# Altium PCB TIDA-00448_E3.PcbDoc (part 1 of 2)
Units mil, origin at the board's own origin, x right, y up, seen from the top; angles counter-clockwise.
Board outline 2125 x 2550 mil, 4 copper layers (Top Layer, MidLayer1, MidLayer2, Bottom Layer), stack 90 mil thick; 140 components, 62 nets, 330 pads, 116 vias.
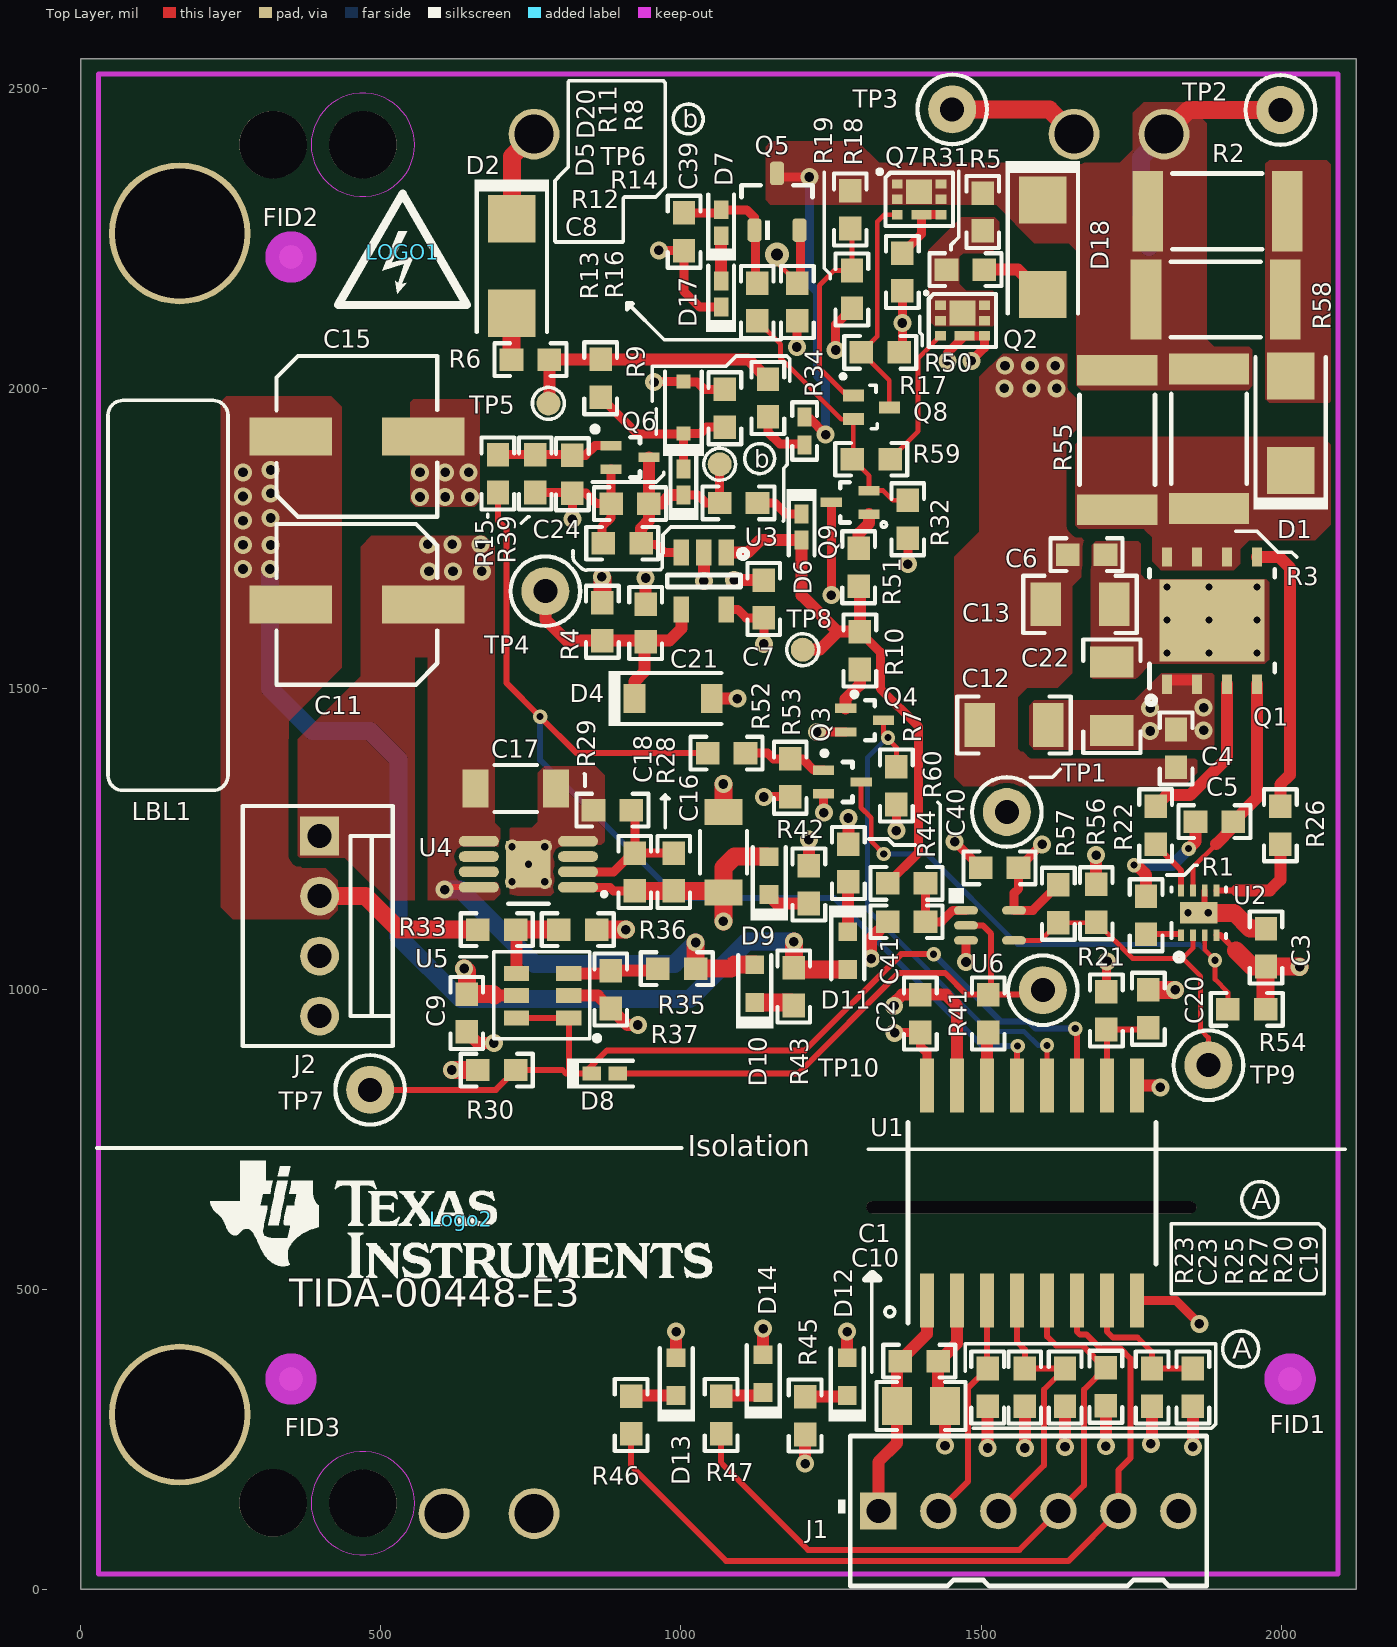
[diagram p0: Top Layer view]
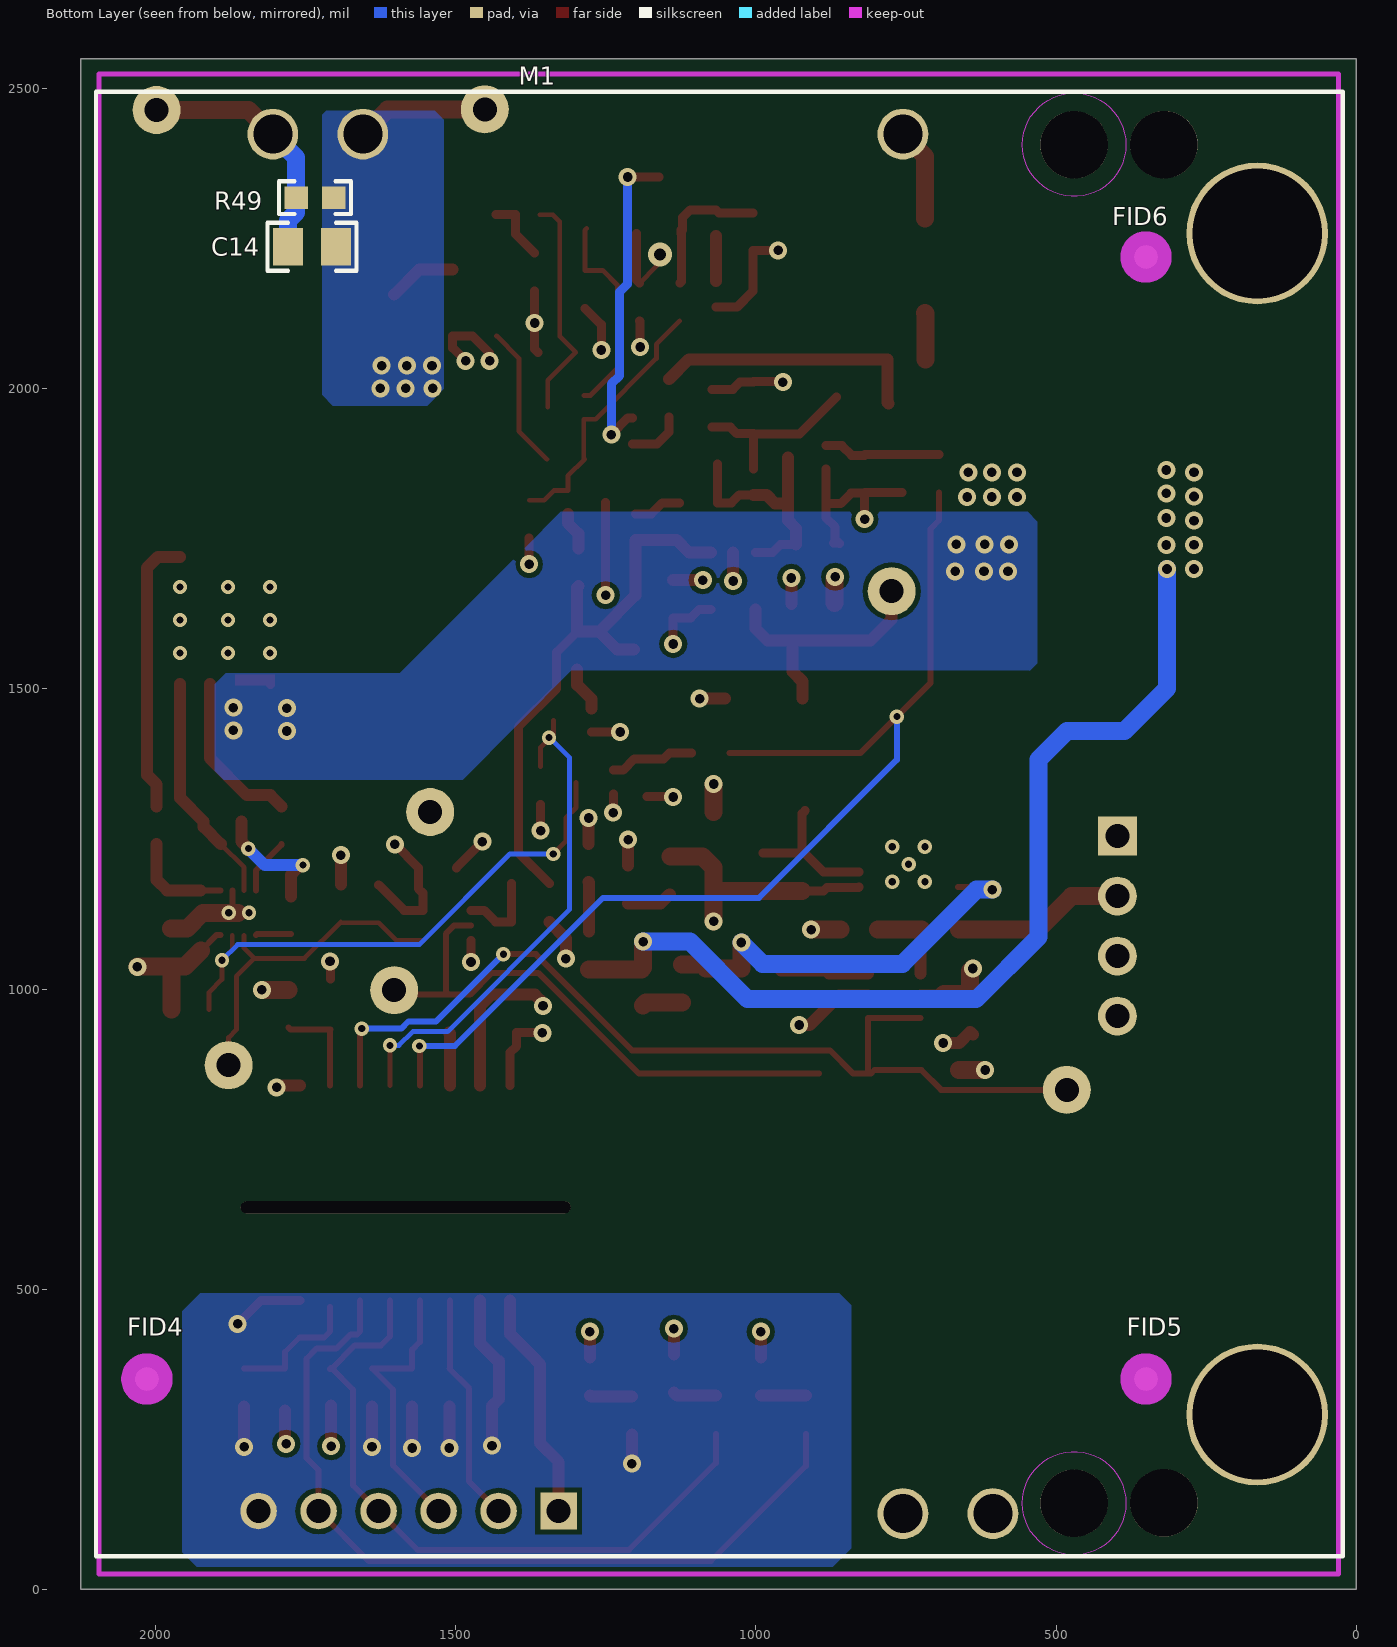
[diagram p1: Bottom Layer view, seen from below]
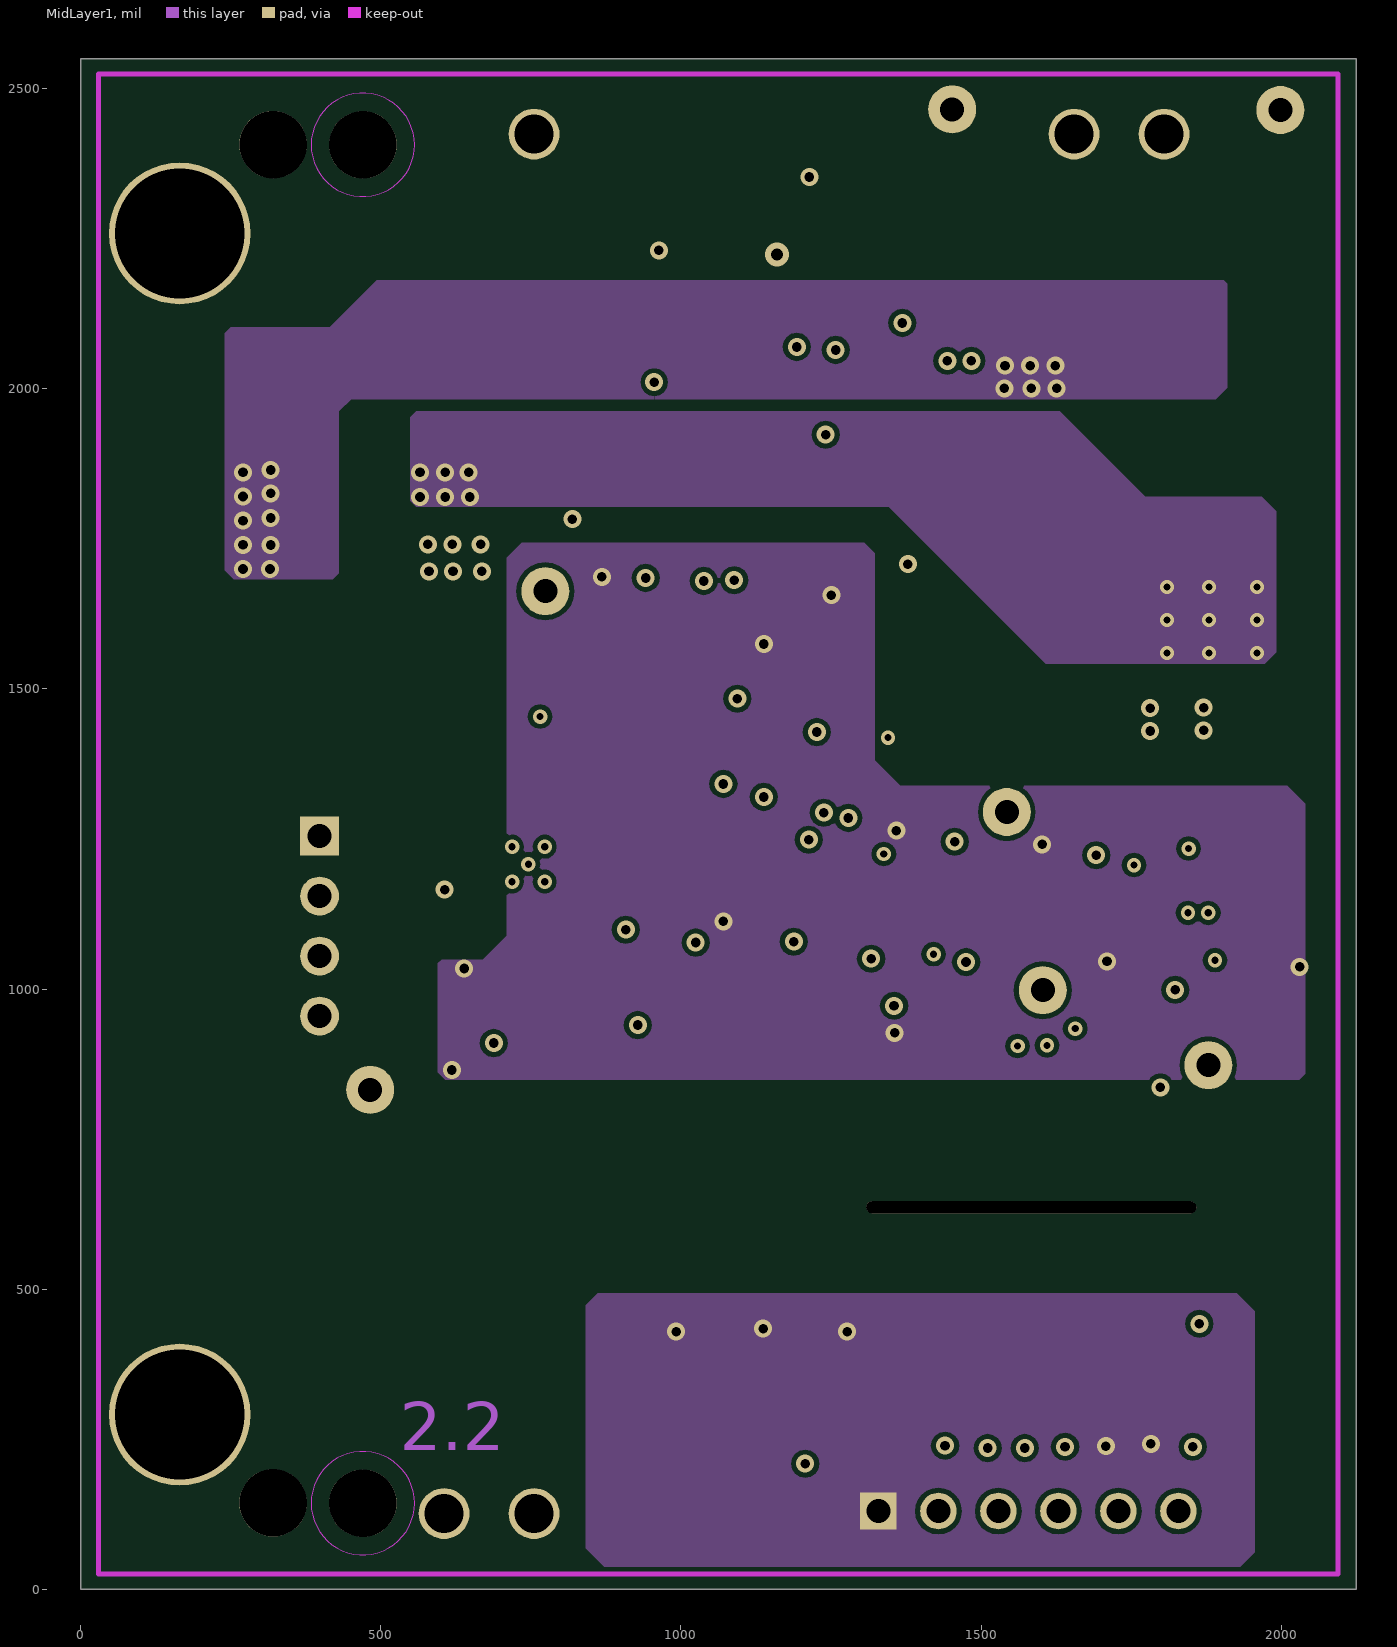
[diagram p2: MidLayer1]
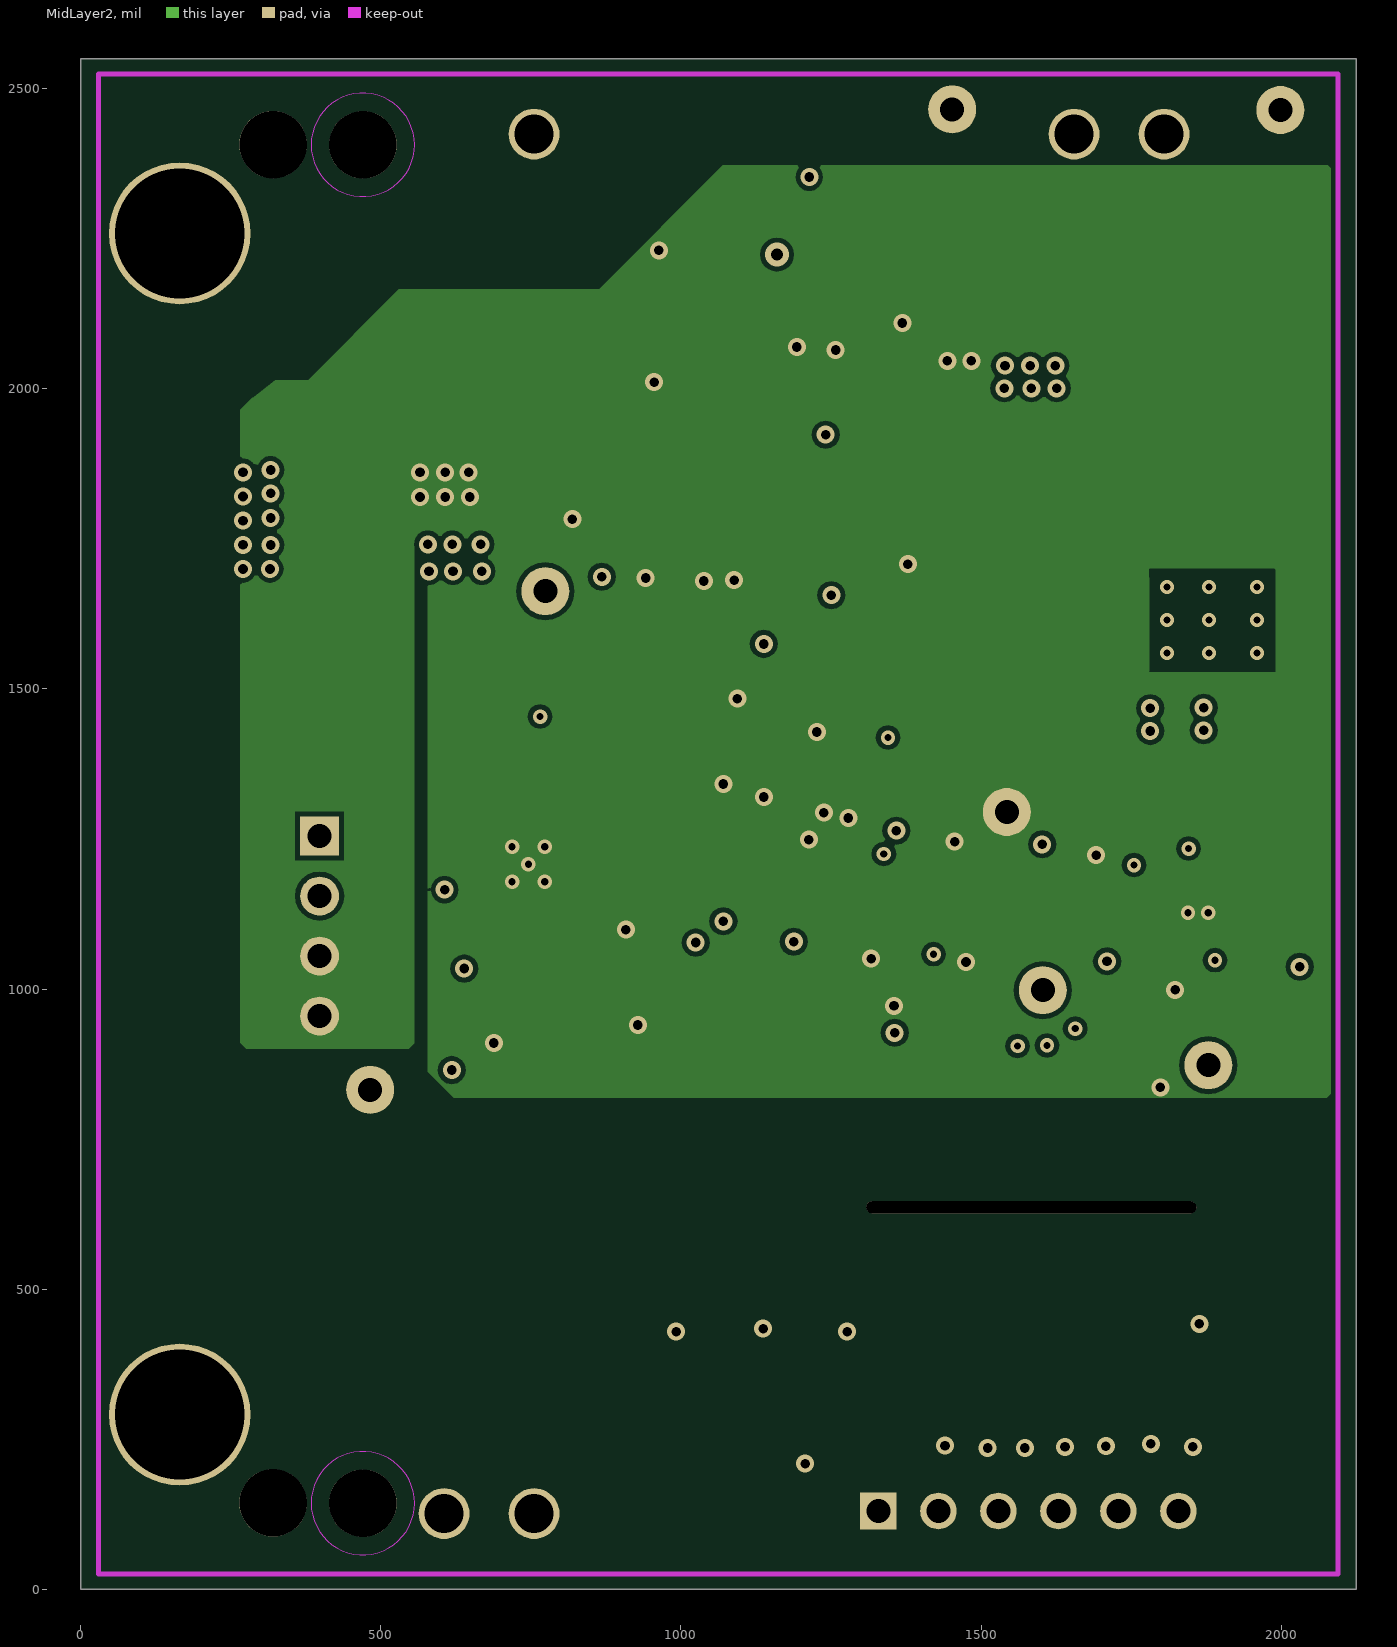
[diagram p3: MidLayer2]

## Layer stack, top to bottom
Top Layer: signal copper 1.4
Dielectric: core 59.2, FR-4, Dk 4.8
MidLayer1: signal copper 1.4
Dielectric: prepreg 12.6, FR-4, Dk 4.8
MidLayer2: signal copper 1.4
Dielectric: core 12.6, FR-4, Dk 4.8
Bottom Layer: signal copper 1.4

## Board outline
0,0 0,2550 2125,2550 2125,0

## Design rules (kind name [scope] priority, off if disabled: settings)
AcuteAngle [All] p1: minimum=4.50000000000000E+0001 checktracksonly=FALSE
AssemblyTestPointUsage [All] p1: valid=2
Clearance Poly_Poly [InPolygon vs InPolygon] p1: gap=15
Clearance "Poly_ All" [InPolygon] p2: gap=8
Clearance "Less Than 9 mils from PAD to PAD" [(InPadClass('Less than 9 Mil Clearance')) vs (InPadClass('Less than 9 Mil Clearance'))] p3: gap=7.8
Clearance "SMT Pin Via" [IsVia vs IsSMTPin] p4: gap=8
Clearance "Via to Via" [IsVia vs IsVia] p5: gap=8
Clearance [All] p6: gap=8
ComponentClearance ComponentClearance_Shunt [InComponentClass('Header') vs InComponentClass('Shunt')] p1: gap=0 collisioncheckmode=3 verticalgap=0 showdistances=FALSE
ComponentClearance ComponentClearance_Logo [InComponentClass('Logo')] p2: gap=50 collisioncheckmode=3 verticalgap=10 showdistances=FALSE
ComponentClearance ComponentClearance_ScrewToNut [(HasFootprint('NY PMS 440 0025 PH')) vs (HasFootprint('Keystone_1902C'))] p3: gap=5 collisioncheckmode=3 verticalgap=10 showdistances=FALSE
ComponentClearance ComponentClearance_MountingHoles [InComponentClass('Mounting Holes')] p4: gap=250 collisioncheckmode=3 verticalgap=100000 showdistances=FALSE
ComponentClearance ComponentClearance_SmallPassives [HasFootprint('0201*') or HasFootprint('0402*') or HasFootprint('0508') or HasFootprint('0603*') or HasFootprint('0612') or HasFootprint('0805*') or HasFootprint('0815*') or HasFootprint('0830*') or HasFootprint('1206*') or HasFootprint('1210*') or HasFootprint('1808*') or HasFootprint('1812*') or HasFootprint('1825*') or HasFootprint('2010*') or HasFootprint('2220*') or HasFootprint('2225*') or HasFootprint('2512*') or HasFootprint('2728*') or HasFootprint('3518*') vs HasFootprint('0201*') or HasFootprint('0402*') or HasFootprint('0508') or HasFootprint('0603*') or HasFootprint('0612') or HasFootprint('0805*') or HasFootprint('0815*') or HasFootprint('0830*') or HasFootprint('1206*') or HasFootprint('1210*') or HasFootprint('1808*') or HasFootprint('1812*') or HasFootprint('1825*') or HasFootprint('2010*') or HasFootprint('2220*') or HasFootprint('2225*') or HasFootprint('2512*') or HasFootprint('2728*') or HasFootprint('3518*')] p5: gap=20 collisioncheckmode=3 verticalgap=10 showdistances=FALSE
ComponentClearance ComponentClearance_THtoSMT [IsThruComponent vs IsSMTComponent] p6: gap=100 collisioncheckmode=3 verticalgap=30 showdistances=FALSE
ComponentClearance ComponentClearance_THtoTH [IsThruComponent vs IsThruComponent] p7: gap=118.11 collisioncheckmode=3 verticalgap=30 showdistances=FALSE
ComponentClearance [All] p8: gap=40 collisioncheckmode=3 verticalgap=10 showdistances=FALSE
DiffPairsRouting [All] p1: maxlimit=100 minlimit=10 mostfreqgap=10 maxuncoupledlength=1000
FabricationTestPointUsage TestPointUsage [All] p1: valid=2 allowmultiple=FALSE
FabricationTestpoint Testpoint [All] p1: side=3 testpointundercomponent=TRUE minsize=40 maxsize=100 preferedsize=60 minholesize=0 maxholesize=40 preferedholesize=32 testpointgrid=1 allowsidetop=TRUE allowsidebottom=TRUE usegrid=TRUE gridtolerance=0.01
FanoutControl Fanout_LCC [IsLCC] p1: bgadir=Out bgaviamode=Centered fanoutstyle=Auto fanoutdirection=Alternating viagrid=1 // Fanout_LCC (Default Rule)
FanoutControl Fanout_BGA [IsBGA] p2: bgadir=Out bgaviamode=Centered fanoutstyle=Auto fanoutdirection=Alternating viagrid=1 // Fanout_BGA (Default Rule)
FanoutControl Fanout_Default [All] p4: bgadir=Out bgaviamode=Centered fanoutstyle=Auto fanoutdirection=Alternating viagrid=1 // Fanout_Default (Default Rule)
FanoutControl Fanout_Small [(CompPinCount < 5)] p5: bgadir=Out bgaviamode=Centered fanoutstyle=Auto fanoutdirection=OutThenIn viagrid=1 // Fanout_Small (Default Rule)
HoleSize [All] p1: absolutevalues=TRUE maxlimit=251 minlimit=7.87 maxpercent=80.000 minpercent=20.000
MinimumAnnularRing MinimumAnnularRing_ThermalPadVias [IsVia and InAnyComponent] p1: minimumring=5.91
MinimumAnnularRing [All] p2: minimumring=5.91
MinimumSolderMaskSliver MinimumSolderMaskSliver_Logo [InComponentClass('Logo') vs InComponentClass('Logo')] p1: minsoldermaskwidth=0.7
MinimumSolderMaskSliver [All] p2: minsoldermaskwidth=3.94
PlaneConnect [All] p1: planeconnectstyle=Relief reliefexpansion=10 reliefentries=4 reliefconductorwidth=10 reliefairgap=10
PolygonConnect [All] p1: connectstyle=Direct reliefconductorwidth=10 reliefentries=4 polygonreliefangle="90 Angle" airgapwidth=10
RoutingVias [All] p1: holewidth=16 width=30 viastyle="Through Hole" minholewidth=12 minwidth=24 maxholewidth=20 maxwidth=40
SMDToCorner [All] p1: distance=30000
SilkToSilkClearance [All] p1: silktosilkclearance=5
SilkscreenOverComponentPads [IsPad] p1: minsilkscreentomaskgap=5
SolderMaskExpansion [All] p1: expansion=2.5
Width Width_power [InNetClass('POWER')] p1: maxlimit=100 minlimit=10 preferedwidth=30
Width [All] p2: maxlimit=100 minlimit=8 preferedwidth=8 checkconnectedcopper=TRUE
14 further rules are at their usual default settings.

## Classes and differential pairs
net class POWER: 0V "3.3V/ 5V" +15V -3V -8V GND
pad class "Less than 9 Mil Clearance": U4-1 U4-2 U4-3 U4-4 U4-5 U4-6 U4-7 U4-8 U4-9
component class Page2_Hardware_ANSI-B: !PCB FID1 FID2 FID3 FID4 FID5 FID6 LBL1 LOGO1 Logo2 ZZ1 ZZ2 ZZ3 ZZ4
component class Page1: C1 C2 C3 C4 C5 C6 C7 C8 C9 C10 C11 C12 C13 C14 C15 C16 C17 C18 C19 C20 C21 C22 C23 C24 C39 C40 C41 D1 D2 D4 D5 D6 D7 D8 D9 D10 D11 D12 D13 D14 D17 D18 D20 J1 J2 M1 Q1 Q2 Q3 Q4 Q5 Q6 Q7 Q8 Q9 R1 R2 R3 R4 R5 R6 R7 R8 R9 R10 R11 R12 R13 R14 R15 R16 R17 R18 R19 R20 R21 R22 R23 R25 R26 R27 R28 R29 R30 R31 R32 R33 R34 R35 R36 R37 R39 R41 R42 R43 R44 R45 R46 R47 R49 R50 R51 R52 R53 R54 R55 R56 R57 R58 R59 R60 TP1 TP2 TP3 TP4 TP5 TP6 TP7 TP8 TP9 TP10 U1 U2 U3 U4 U5 U6

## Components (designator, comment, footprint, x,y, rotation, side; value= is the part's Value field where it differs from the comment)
C1 "06035C104KAT2A" 0603 1397,380 r0 top
C2 "06035C104KAT2A" 0603 1399,959 r90 top
C3 "06035C104KAT2A" 0603 1975,1069 r90 top
C4 "06035C104KAT2A" 0603 1825,1401 r270 top
C5 "UMK107AB7105KA-T" 0603 1889,1279 r0 top
C6 "06035C104KAT2A" 0603 1676,1724 r0 top
C7 "06035C104KAT2A" 0603 1138,1650 r90 top
C8 "06035A471JAT2A" 0603 902,1743 r180 top
C9 "06035C104KAT2A" 0603 643,960 r270 top
C10 "08055C105KAT2A" 0805_HV 1400,305 r0 top
C11 "UUD1E101MCL1GS" SM_RADIAL_6.3BMM 460,1641 r180 top
C12 "GMK316AB7106KL" 1206 1555,1440 r180 top
C13 "GMK316AB7106KL" 1206 1665,1641 r0 top
C14 "DNP" 0805_HV 1740,2237 r180 bottom
C15 "UUD1E101MCL1GS" SM_RADIAL_6.3BMM 460,1921 r0 top
C16 "UMK316AB7475KL-T" 1206_190 1070.73,1228 r90 top
C17 "UMK316AB7475KL-T" 1206_190 724.55,1334 r0 top
C18 "06035A102KAT2A" 0603 923,1195 r90 top
C19 "06035C104KAT2A" 0603 1853,336 r270 top
C20 "06035C104KAT2A" 0603 1779,967 r90 top
C21 "06035C104KAT2A" 0603 941,1610 r90 top
C22 "GMK316AB7106KL" 1206 1718,1488 r90 top
C23 "GRM1885C1H750JA01D" 0603 1573,336 r90 top
C24 "GRM1885C1H750JA01D" 0603 819,1858 r90 top
C39 "06035A560FAT2A" 0603 1005,2262 r270 top
C40 "06035C104KAT2A" 0603 1531,1202 r180 top
C41 "GRM1885C1H750JA01D" 0603 1376,1112 r0 top
D1 "MBRA340T3G" SMA 2016,1943 r90 top
D2 "BYG23T-M3/TR" SMA 718,2205 r270 top
D4 "MMSZ4683-V" SOD-123 987,1484 r0 top
D5 "1N4148X-TP" SOD-523 1004,1845 r90 top
D6 "1N4148X-TP" SOD-523 1201,1770 r270 top
D7 "1N4148X-TP" SOD-523 1067,2277 r90 top
D8 "1N4148X-TP" SOD-523 873,859 r0 top
D9 "150060GS75000" WL-SMCW_GREEN 1147,1189 r90 top
D10 "150060GS75000" WL-SMCW_GREEN 1123,1009 r90 top
D11 "150060GS75000" WL-SMCW_GREEN 1278,1064 r270 top
D12 "150060GS75000" WL-SMCW_GREEN 1277,354 r90 top
D13 "150060YS75000" WL-SMCW_YELLOW 992,354 r90 top
D14 "150060SS75000" WL-SMCW_RED 1137,359 r90 top
D17 "1N4148X-TP" SOD-523 1067,2158 r90 top
D18 "3SMAJ5926B" SMA 1603,2236 r270 top
D20 "MMSZ5234BS-7-F" sod-323 1004,1969 r90 top
FID1 "Fiducial" Fiducial10-20 2015,350 r90 top
FID2 "Fiducial" Fiducial10-20 350,2220 r90 top
FID3 "Fiducial" Fiducial10-20 350,350 r90 top
FID4 "Fiducial" Fiducial10-20 2015,350 r90 bottom
FID5 "Fiducial" Fiducial10-20 350,350 r90 bottom
FID6 "Fiducial" Fiducial10-20 350,2220 r90 bottom
J1 "22-23-2061" Molex_22-23-2061 1579,130 r0 top
J2 "0022112042" CONN_22112042 397.75,1104.8 r270 top
LBL1 "Size: 0.65\" x 0.20 \"" Label_650x200 145,1656 r90 top
LOGO1 "DANGER HIGH VOLTAGE" IEC_HighVoltage_Small 536,2228 r0 top
Logo2 "Texas Instruments" TI_Stacked_Overlay_Small 634,616 r0 top
M1 "CM450DX-24S1" MITSUBISHI_CM450DX-24S1 2330,1275 r180 bottom locked
Q1 "CSD87350Q5D" DQY0008A 1885,1614 r90 top
Q2 "CSD17313Q2" TRANS_NexFET_Q2 1469,2114 r0 top
Q3 "MMBT3904T-7-F" SOT-523#1 1269,1345 r0 top
Q4 "MMBT3904T-7-F" SOT-523#1 1306,1448 r0 top
Q5 "DSS4160T" SOT-23 1160,2312 r90 top
Q6 "MMBT3904T-7-F" SOT-523#1 915,1886 r0 top
Q7 "CSD17313Q2" TRANS_NexFET_Q2 1397,2316 r0 top
Q8 "TR-MMBT3906T-7-F" SOT-523#2 1315,1970 r270 top
Q9 "MMBT3904T-7-F" SOT-523#1 1282,1811 r180 top
R1 "CRCW060310R0JNEA" 0603 1775,1123 r270 top
R2 "CRCW25121R00FKEG" 2512 1894,2296 r0 top
R3 "CRCW25122R00FKEG" 2512 1880,1917 r90 top
R4 "RC0603JR-074K7L" 0603 869,1612 r90 top
R5 "CRCW0603390RJNEA" 0603 1503,2295 r90 top
R6 "CRCW0603150RJNEA" 0603 749,2049 r0 top
R7 "RC0603JR-074K7L" 0603 1359,1339 r270 top
R8 "CRCW06031K00JNEA" 0603 1145,1985 r90 top
R9 "CRCW06032K20JNEA" 0603 866,2018 r90 top
R10 "RC0603JR-074K7L" 0603 1298,1564 r270 top
R11 "CRCW06031K80JNEA" 0603 1073,1968 r270 top
R12 "CRCW06031K80JNEA" 0603 915,1809 r0 top
R13 "CRCW0603330RJNEA" 0603 1127,2145 r270 top
R14 "CRCW06031K00JNEA" 0603 1096,1810 r0 top
R15 "CRCW06031K00JNEA" 0603 695,1859 r90 top
R16 "CRCW060320R0JNEA" 0603 1194,2145 r90 top
R17 "RC0603JR-074K7L" 0603 1332,2061 r180 top
R18 "CRCW060310K0JNEA" 0603 1282,2299 r270 top
R19 "RC0603JR-074K7L" 0603 1285,2166 r90 top
R20 "RC0603JR-074K7L" 0603 1785,336 r270 top
R21 "RC0603JR-074K7L" 0603 1709,964 r270 top
R22 "CRCW06030000Z0EA" 0603 1791,1273 r90 top
R23 "RC0603JR-074K7L" 0603 1511,336 r270 top
R25 "RC0603JR-074K7L" 0603 1640,336 r270 top
R26 "CRCW06030000Z0EA" 0603 1999,1273 r90 top
R27 "RC0603JR-074K7L" 0603 1708,337 r270 top
R28 "CRCW0603332KFKEA" 0603 988,1195 r270 top
R29 "CRCW0603100KFKEA" 0603 885.73,1298 r0 top
R30 "CRCW0603100KJNEA" 0603 693,865 r180 top
R31 "CRCW060315R0JNEA" 0603 1474,2199 r0 top
R32 "CRCW06031K00JNEA" 0603 1378,1783 r90 top
R33 "RC0603FR-07220KL" 0603 693,1099 r180 top
R34 "CRCW04020000Z0ED" 0402 1206,1930 r270 top
R35 "RC0603FR-07220KL" 0603 993,1034 r0 top
R36 "RC0603FR-079K76L" 0603 828,1099 r180 top
R37 "RC0603FR-074K12L" 0603 883,999 r90 top
R39 "RC0603JR-0715KL" 0603 757,1859 r270 top
R41 "CRCW06031K00JNEA" 0603 1512,959 r270 top
R42 "RC0603JR-072K2L" 0603 1213,1174 r270 top
R43 "CRCW060310K0JNEA" 0603 1188,1004 r90 top
R44 "RC0603JR-074K7L" 0603 1279,1210 r270 top
R45 "CRCW06031K00JNEA" 0603 1207,289 r90 top
R46 "CRCW0603330RJNEA" 0603 917,290 r90 top
R47 "CRCW0603330RJNEA" 0603 1067,290 r90 top
R49 "CRCW060310K0JNEA" 0603 1735,2319 r0 bottom
R50 "CRCW060320R0JNEA" 0603 1369,2195 r90 top
R51 "RC0603JR-074K7L" 0603 1296,1703 r90 top
R52 "CRCW06031K00JNEA" 0603 1076,1393 r0 top
R53 "RC0603JR-0715KL" 0603 1182,1352 r270 top
R54 "RC0603JR-074K7L" 0603 1943,966 r180 top
R55 "CRCW25122R00FKEG" 2512 1727,1915 r90 top
R56 "CRCW06031K00JNEA" 0603 1692,1143 r270 top
R57 "RC0603JR-072K2L" 0603 1629,1142 r90 top
R58 "CRCW25121R00FKEG" 2512 1891,2149 r0 top
R59 "CRCW060310R0FKEAHP" 0603 1317,1883 r180 top
R60 "CRCW0603470RJNEA" 0603 1376,1176 r0 top
TP1 "5000" Keystone5000 1543,1295 r0 top
TP2 "5000" Keystone5000 1999,2465 r0 top
TP3 "5000" Keystone5000 1452,2466 r0 top
TP4 "5000" Keystone5000 774,1663 r90 top
TP5 "TP_40_SMT" TP_40_SMT 779,1976 r90 top
TP6 "TP_40_SMT" TP_40_SMT 1064.5,1874.5 r90 top
TP7 "5000" Keystone5000 482,832 r90 top
TP8 "TP_40_SMT" TP_40_SMT 1203,1565.5 r0 top
TP9 "5000" Keystone5000 1879,873 r0 top
TP10 "5000" Keystone5000 1603,998 r90 top
U1 "ISO7842DWR" DW0016B_N 1585,660 r90 top
U2 "TPS51604DSG" DSG0008A 1863,1127 r90 top
U3 "TLV3201DBV" DBV0005A_N 1038,1680 r270 top
U4 "TPS7A4201DGNT" DGN0008B_N 745.73,1208 r180 top
U5 "TPS3700DDC" SOT23-6 768,989 r180 top
U6 "SN74LVC1G125DCK" SOP_5P.65MM(DCK) 1515,1106 r270 top
ZZ1 "This Assembly Note is for PCB labels only" AssemblyNoteLabel -307,2615 r0 top
ZZ2 "These assemblies are ESD sensitive, ESD precautions shall be observed." AssemblyNote -307,2830 r0 top
ZZ3 "These assemblies must be clean and free from flux and all contaminants. Use of no clean flux is not acceptable." AssemblyNote -307,2760 r0 top
ZZ4 "These assemblies must comply with workmanship standards IPC-A-610 Class 2, unless otherwise specified." AssemblyNote -307,2690 r0 top

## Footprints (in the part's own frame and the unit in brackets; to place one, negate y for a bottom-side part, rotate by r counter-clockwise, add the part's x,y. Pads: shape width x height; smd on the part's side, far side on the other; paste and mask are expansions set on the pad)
0402 [mm] "0402 from SM-752 data"
  rect 0.8x0.6 smd: 1(-0.6,0) 2(0.6,0)
  silkscreen extent -1.22,-0.52 1.22,0.52, body extent -0.55,-0.3 0.55,0.3, height 0.6
0603 [mm] "0603 from SM-752 data"
  rect 1x0.95 smd: 1(-0.8,0) 2(0.8,0)
  silkscreen extent -1.52,-0.69 1.52,0.69, body extent -0.87,-0.47 0.87,0.47, height 0.85
0805_HV [mil] "0805 with 30mil clearance between pads"
  rect 50x63 smd: 1(-40,0) 2(40,0)
  silkscreen extent -74,-40 74,40, body extent -43,-29 43,29, height 43
1206 [mm] "1206 from SM-752 data"
  rect 1.3x1.85 smd: 1(-1.45,0) 2(1.45,0)
  silkscreen extent -2.4,-1.21 2.4,1.21, body extent -1.7,-0.9 1.7,0.9, height 1.35
1206_190 [mm] "1206_190"
  rect 1.1x1.6 smd: 1(-1.7,0) 2(1.7,0)
  silkscreen extent -0.9,-1 0.9,1, body extent -1.75,-0.95 1.75,0.95, height 1.9
2512 [mm] "Chip Resistor, Body 6.3x3.2mm, IPC Medium Density"
  rect 1.3x3.4 smd: 1(-2.95,0) 2(2.95,0)
  silkscreen extent -1.9,-1.6 1.9,1.6, body extent -3.22,-1.67 3.22,1.67, height 0.71
AssemblyNote [mil] "Assembly Note"
AssemblyNoteLabel [mil] "Assembly Note for PCB Labels"
CONN_22112042 [mm] "Molex"
  rect 1.65x1.65 hole 1.016: 1(-3.81,0)
  round 1.65 hole 1.016: 2(-1.27,0) 3(1.27,0) 4(3.81,0)
  silkscreen extent -5.08,-3.25 5.08,3.1, body extent -5,-3.25 5,3.1, height 10.68
DBV0005A_N [mm] "SOT23, 5-Leads, Body 2.9x1.6mm, Pitch 0.95mm, Lead Span 2.8mm, IPC Medium Density"
  rect 1.1x0.65 smd: 1(-1.2,0.95) 2(-1.2,0) 3(-1.2,-0.95) 4(1.2,-0.95) 5(1.2,0.95)
  silkscreen extent -0.25,-1.55 0.25,1.55, body extent -1.42,-1.46 1.42,1.46, height 1.08
DGN0008B_N [mm] "TSOP, 8-Leads, Body 3x3mm, Pitch 0.65mm, Thermal Pad 1.92x1.60mm, IPC Medium Density"
  oval 1.7x0.45 smd mask+0.05: 1(-2.1,0.975) 2(-2.1,0.325) 3(-2.1,-0.325) 4(-2.1,-0.975) 5(2.1,-0.975) 6(2.1,-0.325) 7(2.1,0.325) 8(2.1,0.975)
  rect 1.88x1.98 smd mask+0.05: 9(0,0)
  silkscreen extent -0.85,1.68 0.85,1.68, body extent -2.45,-1.5 2.45,1.5, height 0.94
DQY0008A [mm]
  rect 0.81x0.41 smd: 1(-2.692,1.905) 2(-2.692,0.635) 3(-2.692,-0.635) 4(-2.692,-1.905) 5(2.692,-1.905) 6(2.692,-0.635) 7(2.692,0.635) 8(2.692,1.905)
  rect 3.48x4.46 smd paste-2.217: 9(0,0)
  Top Layer region: -2.737,0.43 -2.287,0.43 -2.287,2.11 -2.737,2.11
  silkscreen extent -2.85,-2.65 2.18,2.65, body extent -3.1,-2.6 3.1,2.6, height 1.51
DSG0008A [mm] "SON, 8-Leads, Body 2x2mm, Pitch 0.5mm, Thermal Pad 1.6x0.9mm, TI Recommended"
  rect 0.5x0.25 smd: 1(-0.95,0.75) 2(-0.95,0.25) 3(-0.95,-0.25) 4(-0.95,-0.75) 5(0.95,-0.75) 6(0.95,-0.25) 7(0.95,0.25) 8(0.95,0.75)
  rect 0.9x1.6 smd paste-0.45: 9(0,0)
  silkscreen extent -1.07,-1.15 1.07,1.15, body extent -1.05,-1.05 1.05,1.05, height 0.8
DW0016B_N [mm] "SOP, 16-Leads, Body 10.5x7.6mm (max), Pitch 1.27mm, IPC Medium Density"
  rect 2.3x0.6 smd: 1(-4.55,4.445) 2(-4.55,3.175) 3(-4.55,1.905) 4(-4.55,0.635) 5(-4.55,-0.635) 6(-4.55,-1.905) 7(-4.55,-3.175) 8(-4.55,-4.445) 9(4.55,-4.445) 10(4.55,-3.175) 11(4.55,-1.905) 12(4.55,-0.635) 13(4.55,0.635) 14(4.55,1.905) 15(4.55,3.175) 16(4.55,4.445)
  silkscreen extent -5.5,-5.25 3,5.25, body extent -3.8,-5.25 3.8,5.25, height 2.66
Fiducial10-20 [mm]
  round 1 smd mask+0.5: 1(0,0)
  Top Layer keep-out circle w1.178: c0,0 r0.5
IEC_HighVoltage_Small [mil]
  silkscreen extent -107,-88 107,97
Keystone5000 [mil] "For Keystone 500x miniature loop terminals"
  round 80 hole 40: 1(0,0)
  silkscreen extent -58,-58 58,58, body extent -49,-49 49,49, height 182
Label_650x200 [mil] "Thermal Transfer Label"
  round 1 on Mech13: 0(0,0)
  silkscreen extent -325,-100 325,100, body extent -326,-101 326,101, height 1
MITSUBISHI_CM450DX-24S1 [mm] "IGBT, MOD NX, 450A, 1200V, DUAL"
  round 2.15 hole 1.65: 3(13.33,29.2) 4(17.14,29.2) 5(40,29.2)
  round 2.854 hole 2.854 unplated mask+0.127: ""(47.25,-28.75) ""(47.25,28.75)
  round 6 hole 5.5 unplated mask+0.127: ""(55,-25) ""(55,25)
  Keep-Out Layer circle w0.05: c47.25,-28.75 r2.189
  Keep-Out Layer circle w0.05: c47.25,28.75 r2.189
  silkscreen extent 5.84,-31 58.62,31, body extent -76,-31 76,31, height 17
Molex_22-23-2061 [mm] "Header, 2.54mm, 6x1, TH"
  rect 1.55x1.55 hole 1.02: 1(-6.35,0)
  round 1.55 hole 1.02: 2(-3.81,0) 3(-1.27,0) 4(1.27,0) 5(3.81,0) 6(6.35,0)
  silkscreen extent -8.05,-3.18 7.54,3.17, body extent -7.54,-3.25 7.54,3.1, height 10.67
SM_RADIAL_6.3BMM [mm] "Nichicon 6.3x7.7"
  rect 3.5x1.6 smd: 1(-2.8,0) 2(2.8,0)
  silkscreen extent -3.4,-3.4 3.4,3.4, body extent -3.41,-3.41 3.41,3.41, height 8
SMA [mm] "Molded Diode, 2-Leads, Body 4.3x2.6mm, IPC Medium Density, based on OnSemi component dimensions and land pattern"
  rect 2x2 smd: 1(-2,0) 2(2,0)
  silkscreen extent -3.66,-1.57 2.79,1.57, body extent -2.6,-1.3 2.6,1.3, height 2.42
SOD-123 [mm] "On Semi recommended land pattern"
  rect 0.915x1.22 smd: 1(-1.637,0) 2(1.637,0)
  silkscreen extent -2.74,-1.17 2.03,1.17, body extent -1.93,-0.9 1.93,0.9, height 1.35
sod-323 [mm] "NXP recommended land pattern"
  rect 0.6x0.6 smd paste-0.05: 1(-1.1,0) 2(1.1,0)
  silkscreen extent -2.06,-0.86 1.53,0.86, body extent -1.3,-0.67 1.3,0.68, height 1.1
SOD-523 [mm] "NXP Semiconductor recommended land pattern, nominal STEP model"
  rect 0.8x0.6 smd paste-0.05: 1(-0.55,0) 2(0.55,0)
  silkscreen extent -1.6,-0.64 1.2,0.63, body extent -0.8,-0.4 0.8,0.4, height 0.72
SOP_5P.65MM(DCK) [mil]
  oval 14x40 smd: 1(-25,-40) 2(0,-40) 3(25,-40) 4(25,40) 5(-25,40)
  silkscreen extent -62,-69 -37,-44
SOT23-6 [mil]
  rect 42x25 smd: 1(-45,37) 2(-45,0) 3(-45,-37) 4(42,-37) 5(42,0) 6(42,37)
SOT-23 [mm] "SOT23, 3-Leads, Body 2.9x1.3mm, Pitch 0.95mm, Lead Span 2.5mm, IPC Medium Density"
  rrect50% 1x0.6 smd: 1(-1.2,0.95) 2(-1.2,-0.95) 3(1.2,0)
  silkscreen extent -1.62,-1.5 0.7,1.5, body extent -1.16,-1.45 1.21,1.45, height 1
SOT-523#1 [mm] "From Diodes Inc datasheet component parameters"
  rect 0.9x0.4 smd: 1(-0.8,0.5) 2(-0.8,-0.5) 3(0.8,0)
  silkscreen extent 0.02,-0.85 0.42,0.85, body extent -0.8,-0.8 0.8,0.8, height 0.79
SOT-523#2 [mm]
  rect 0.508x0.889 smd: 1(-0.485,-0.706) 2(0.516,-0.706) 3(0.015,0.818)
TI_Stacked_Overlay_Small [mil]
  silkscreen extent -418,-98 418,98
TP_40_SMT [mil]
  round 40 smd: 1(0,0)
TRANS_NexFET_Q2 [mm] "TI recommended land pattern M0167-01"
  rect 0.46x0.4 smd mask+0.051: 1(-0.93,0.65) 2(-0.93,0) 3(-0.93,-0.65) 4(0.93,-0.65) 5(0.93,0) 6(0.93,0.65)
  rect 0.85x0.4 smd paste-0.025 mask+0.051: 7(0.095,-0.65)
  rect 1.1x1.05 smd paste-0.05: 8(0,0.325)
  silkscreen extent -1.43,-1.12 1.43,1.12, body extent -1,-1 1,1, height 0.85
WL-SMCW_GREEN [mm] "WURTH"
  rect 0.8x0.8 smd: 1(-0.8,0) 2(0.8,0)
  silkscreen extent -1.9,-0.8 1.2,0.8, body extent -0.85,-0.45 0.85,0.45, height 0.8
WL-SMCW_RED [mm] "WURTH"
  rect 0.8x0.8 smd: 1(-0.8,0) 2(0.8,0)
  silkscreen extent -1.9,-0.8 1.2,0.8, body extent -0.85,-0.45 0.85,0.45, height 0.8
WL-SMCW_YELLOW [mm] "WURTH"
  rect 0.8x0.8 smd: 1(-0.8,0) 2(0.8,0)
  silkscreen extent -1.9,-0.8 1.2,0.8, body extent -0.85,-0.45 0.85,0.45, height 0.8

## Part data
C1 C2 C3 C4 C6 C7 C9 C19 C20 C21 C40: "CAP, CERM, 0.1 µF, 50 V, +/- 10%, X7R, 0603"
C5: "CAP, CERM, 1 µF, 50 V, +/- 10%, X7R, 0603"
C8: "CAP, CERM, 470 pF, 50 V, +/- 5%, C0G/NP0, 0603"
C10: "CAP, CERM, 1 µF, 50 V, +/- 10%, X7R, 0805"
C11 C15: "CAP, AL, 100 µF, 25 V, +/- 20%, 0.34 ohm, SMD"
C12 C13 C22: "CAP, CERM, 10 µF, 35 V, +/- 10%, X7R, 1206"
C14: library part 08055C105KAT2A
C16 C17: "CAP, CERM, 4.7 µF, 50 V, +/- 10%, X7R, 1206_190"
C18: "CAP, CERM, 1000 pF, 50 V, +/- 10%, C0G/NP0, 0603"
C23 C24 C41: "CAP, CERM, 75 pF, 50 V, +/- 5%, C0G/NP0, 0603"
C39: "CAP, CERM, 56 pF, 50 V, +/- 1%, C0G/NP0, 0603"
D1: "Diode, Schottky, 40 V, 3 A, SMA"
D2: "Diode, Ultrafast, 1300 V, 1 A, SMA"
D4: "Diode, Zener, 3 V, 500 mW, SOD-123"
D5 D6 D7 D8 D17: "Diode, Switching, 75 V, 0.3 A, SOD-523"
D9 D10 D11 D12: "LED, Green, SMD"
D13: "LED, Yellow, SMD"
D14: "LED, Super Red, SMD"
D18: "Diode, Zener, 11 V, DO-214AC"
D20: "Diode, Zener, 6.2 V, 200 mW, SOD-323"
FID1 FID2 FID3 FID4 FID5 FID6: "Fiducial mark.  There is nothing to buy or mount."
J1: "Header, 2.54 mm, 6x1, Tin, TH"
J2: "Header (friction lock), 100mil, 4x1, Gold, TH"
LBL1: library part THT-14-423-10, "Thermal Transfer Printable Labels, 0.650\" W x 0.200\" H - 10,000 per roll"
LOGO1: library part IEC_HighVoltage, "IEC 61010-1 High Voltage Warning"
Logo2: library part TI_Logo, "Texas Instrument Corporate Signature"
M1: "IGBT, MOD NX, 450A, 1200V, DUAL"
Q1: "Synchronous Buck NexFET Power Block, DQY0008A"
Q2 Q7: "MOSFET, N-CH, 30 V, 5 A, SON 2x2mm"
Q3 Q4 Q6 Q9: library part "MMBT3904T-7-F, Diodes Inc.", "Transistor, NPN, 40 V, 0.2 A, SOT-523"
Q5: "TRANSISTOR, NPN, 60V, 1A, SOT23-3"
Q8: "Bipolar, PNP, -40V, -200mA, -200mW"
R1: "RES, 10, 5%, 0.1 W, 0603"
R2 R58: "RES, 1.00, 1%, 1 W, 2512"
R3 R55: "RES, 2.00, 1%, 1 W, 2512"
R4 R7 R10 R17 R19 R20 R21 R23 R25 R27 R44 R51 R54: "RES, 4.7 k, 5%, 0.1 W, 0603"
R5: "RES, 390, 5%, 0.1 W, 0603"
R6: "RES, 150, 5%, 0.1 W, 0603"
R8 R14 R15 R32 R41 R45 R52 R56: "RES, 1.0 k, 5%, 0.1 W, 0603"
R9 R42 R57: "RES, 2.2 k, 5%, 0.1 W, 0603"
R11 R12: "RES, 1.8 k, 5%, 0.1 W, 0603"
R13 R46 R47: "RES, 330, 5%, 0.1 W, 0603"
R16 R50: "RES, 20, 5%, 0.1 W, 0603"
R18 R43 R49: "RES, 10 k, 5%, 0.1 W, 0603"
R22 R26: "RES, 0, 5%, 0.1 W, 0603"
R28: "RES, 332 k, 1%, 0.1 W, 0603"
R29: "RES, 100 k, 1%, 0.1 W, 0603"
R30: "RES, 100 k, 5%, 0.1 W, 0603"
R31: "RES, 15, 5%, 0.1 W, 0603"
R33 R35: "RES, 220 k, 1%, 0.1 W, 0603"
R34: "RES, 0, 5%, 0.063 W, 0402"
R36: "RES, 9.76 k, 1%, 0.1 W, 0603"
R37: "RES, 4.12 k, 1%, 0.1 W, 0603"
R39 R53: "RES, 15 k, 5%, 0.1 W, 0603"
R59: "RES, 10.0, 1%, 0.25 W, 0603"
R60: "RES, 470, 5%, 0.1 W, 0603"
TP1 TP2 TP3 TP4 TP7 TP9 TP10: "Test Point, Miniature, Red, TH"
TP5 TP6 TP8: "Test point, 40 mil SMT"
U1: "High-Performance, 8000 VPK Reinforced Quad Channel Digital Isolator, DW0016B"
U2: "Synchronous Buck FET Driver Optimized for High-Frequency Applications, DSG0008A"
U3: "40-ns, microPOWER, Push-Pull Output Comparators, DBV0005A"
U4: "Single Output LDO, 50 mA, Adjustable 1.175 to 26 V Output, 7 to 28 V Input, 8-pin MSOP (DGN), -40 to 125 degC, Green (RoHS & no Sb/Br)"
U5: "IC,  High Voltage, Over-Under Voltage Supervisory"
U6: "IC, Single Bus Buffer Gate With 3-States Outputs, OE  Active Low"
ZZ1: library part AssemblyNoteLabel
ZZ2 ZZ3 ZZ4: library part AssemblyNote

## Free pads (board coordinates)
  oval 550x20 hole 20 slot 550 at 0 deg unplated mask+5: 0(1584,636)
  round 84.65 hole 64.96: 1(605.2,125.79) 2(755.2,125.79)
  round 112.36 hole 112.36 unplated mask+5: ""(320.16,143.5) ""(320.16,2407.28)

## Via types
v1: diameter 30, hole 16, Top Layer to Bottom Layer, tented both sides, 89 vias
v2: diameter 24, hole 12, Top Layer to Bottom Layer, 26 vias
v3: diameter 40, hole 20, Top Layer to Bottom Layer, 1 vias

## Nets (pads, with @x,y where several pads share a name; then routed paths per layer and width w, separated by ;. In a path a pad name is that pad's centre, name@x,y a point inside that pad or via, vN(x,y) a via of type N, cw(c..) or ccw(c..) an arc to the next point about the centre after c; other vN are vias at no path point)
0V: C4.2 C6.1 C11.2 C12.2 C13.1 C14.2 C15.1 D11.2 J2.2 M1.4 R33.2 R43.2 R49.1 TP3.1 | length 2141.7
  Top Layer w30: J2.2@397.75,1154.8 473.8,1154.8 529.6,1099 R33.2@661.5,1099 ; v1(1188,1079) R43.2@1188,1035.5 1190.99,1032.5 D11.2@1278,1032.5 ; TP3.1@1452,2466 1613.8,2466 M1.4@1655.2,2424.61
  Bottom Layer w30: v1(315,1700) 315,1501 386,1430 482,1430 529.26,1382.74 529.26,1086.74 633,983 1014,983 1110,1079 v1(1188,1079)
  other v1: 270,1700 270,1740.25 316,1740 270,1780.5 316,1785 270,1820.75 316,1826 270,1861 316,1865 1539,2001 1584,2001 1626,2001 1540,2039 1582,2039 1624,2039
"3.3V/ 5V": C1.1 C10.1 D12.2 D13.2 D14.2 J1.1 R20.2 R27.2 U1.1 | length 638.8
  Top Layer w20: D13.2@992,385.5 v1(992,429) ; D14.2@1137,390.5 v1(1137,434) ; D12.2@1277,385.5 v1(1277,429) ; J1.1@1329,130 1329,212 1360,243 C10.1@1360,305 1360,374.5 C1.1@1365.5,380 1365.5,380.85 1410,425.35 U1.1@1410,480.87 ; v1(1708,238) R27.2@1708,305.5 ; v1(1783,242) 1785,244 R20.2@1785,297.5
+15V: C4.1 C11.1 C12.1 C17.1 C22.1 D10.2 J2.1 Q1.1 Q1.2 R35.2 U4.5 U4.8 | length 688.5
  Top Layer w10: v1(606,1165.5) 610.12,1169.61 U4.8@663.06,1169.61
  Top Layer w15: Q1.1@1809.5,1507.5 Q1.1@1810,1508
  Top Layer w30: v1(1024.5,1077.5) R35.2@1024.5,1034 1083,1034 1089.5,1040.5 D10.2@1123,1040.5
  Bottom Layer w30: v1(606,1165.5) 632.5,1165.5 756,1042 988.99,1042 v1(1024.5,1077.5)
  other v1: 1782,1430 1871,1431 1782,1468 1871,1469 580,1696 620,1696 668,1696 578,1741 619,1741 666,1741
-3V: C2.1 C3.1 C7.1 C9.1 C16.1 C18.1 C40.1 D9.2 Q9.3 R4.2 R7.2 R21.1 R28.2 R30.2 R54.1 R57.2 U1.16 U2.4 U3.5 U4.1 U5.5 U6.5 | length 1556.7
  Top Layer w10: U2.4@1892.53,1089.6 1899.4,1089.6 1925,1064
  Top Layer w15: U4.1@828.41,1169.61 829.03,1169 881.8,1169 887.3,1163.5 C18.1@923,1163.5 ; U3.5@1075.4,1632.76 1094.24,1632.76 1108.5,1618.5 C7.1@1138,1618.5 v1(1138,1575) ; v1(1250.5,1656.5) Q9.3@1250.5,1811 ; v1(1356,927) 1356.5,927.5 C2.1@1399,927.5 1399,905 1410,894 U1.16@1410,839.13 ; v1(1359,1264) R7.2@1359,1307.5 ; v1(1602,1241) 1601.5,1241 C40.1@1562.5,1202 1562.5,1167.5 1555,1160 U6.5@1555,1131 1586.5,1131 R57.2@1629,1173.5 ; 1709,1017 1709,1045 v1(1710,1046)
  Top Layer w20: 689,989 U5.5@726,989
  Top Layer w30: v1(618,865) R30.2@661.5,865 ; v1(638.58,1034.18) 638.82,1034.18 643,1030 C9.1@643,991.5 686.5,991.5 689,989 ; v1(868,1687) 868,1686 869,1685 R4.2@869,1643.5 ; C18.1@923,1163.5 R28.2@988,1163.5 C16.1@1068.3,1163.5 ; v1(1070.73,1112.73) C16.1@1070.73,1161.07 1070.73,1202.73 1089.07,1221.07 D9.2@1142.43,1221.07 ; 1925,1064 1951.5,1037.5 C3.1@1975,1037.5 ; R54.1@1974.5,966 1974.5,1037 C3.1@1975,1037.5 ; v1(2031,1037) 2030.5,1037.5 C3.1@1975,1037.5
-8V: C2.2 C3.2 C6.2 C7.2 C8.2 C9.2 C13.2 C15.2 C16.2 C17.2 C20.2 C21.2 C22.2 C24.1 C39.2 C40.2 C41.1 D4.2 D17.1 D20.2 J2.3 J2.4 Q1.9 Q2.4 Q2.7 Q3.2 Q4.2 Q6.2 R11.1 R12.1 R16.1 R17.1 R19.1 R29.1 R32.1 R36.1 R37.1 R39.2 R42.1 R44.1 R50.1 R53.2 R56.1 TP1.1 U1.9 U1.15 U2.6 U2.9 U3.2 U4.4 U4.9 U5.2 U6.3 | length 2443.5
  Top Layer w10: U2.9@1863,1127 1872.84,1136.84 U2.6@1872.84,1164.4
  Top Layer w15: R39.2@757,1827.5 818,1827.5 C24.1@819,1826.5 ; v1(819,1783) C24.1@819,1826.5 ; C8.2@861.01,1742.5 C8.2@861.51,1743 ; C8.2@870.5,1743 C8.2@861.51,1743 ; Q6.2@883.5,1866.31 R12.1@883.5,1809 ; v1(955.31,2011.31) 956.31,2012.31 D20.2@1004,2012.31 ; v1(963,2231) 963.5,2230.5 C39.2@1005,2230.5 1005,2163 1031.65,2136.35 D17.1@1067,2136.35 ; D20.2@1004,2011.31 1026.69,2011.31 1038.5,1999.5 R11.1@1073,1999.5 ; v1(1138,1320) 1138.5,1320.5 R53.2@1182,1320.5 ; v1(1193,2070) 1193,2112.5 R16.1@1194,2113.5 ; v1(1226.31,1428.31) Q4.2@1274.5,1428.31 ; Q3.2@1237.5,1325.31 1237.5,1294.5 v1(1238,1294) ; v1(1257.82,2065) 1257.82,2107.32 R19.1@1285,2134.5 ; R17.1@1363.5,2061 1369,2066.5 R50.1@1369,2163.5 ; v1(1378,1708) R32.1@1378,1751.5 ; v1(1444,2047) 1444,2059.67 Q2.7@1472.74,2088.41 Q2.4@1505.61,2088.41 1505.61,2068.61 v1(1484,2047) ; v1(1456,1245.5) C40.2@1499.5,1202 ; v1(1475,1045) U6.3@1475,1081 ; C24.1@819,1826.5 841.5,1826.5 859,1809 R12.1@883.5,1809 ; C8.2@861.51,1743 868,1749.49 868,1770.2 883.5,1785.7 R12.1@883.5,1809
  Top Layer w20: C9.2@638.5,924 C9.2@643,928.5 661.5,910 v1(688,910) ; U5.2@813,989 861.5,989 R37.1@883,967.5 910.5,940 v1(928,940) ; C21.2@941,1641.5 v1(941,1685) ; v1(1038,1680) U3.2@1038,1727.24 ; D4.2@1051.47,1484 v1(1094,1484) ; v1(1088.5,1681.5) C7.2@1138,1681.5 ; R42.1@1213,1205.5 v1(1213,1249) ; R44.1@1279,1241.5 v1(1279,1285) ; v1(1316.75,1050.65) 1316.75,1084.24 C41.1@1344.5,1112 ; v1(1355,972) 1355,977 1368.5,990.5 C2.2@1399,990.5 1441.5,990.5 1460,972 U1.15@1460,839.13 ; R56.1@1692,1174.5 1692,1214 1691,1215 1692,1216 v1(1692,1223) ; U1.9@1760,839.13 1795.87,839.13 v1(1799,836)
  Top Layer w30: R36.1@859.5,1099 v1(908,1099) ; C16.2@1070.73,1294.93 v1(1070.73,1341.73) ; C20.2@1779,998.5 v1(1823.5,998.5) ; U2.9@1863,1127 v2(1878.75,1127) 1922,1127 1948.5,1100.5 C3.2@1975,1100.5
  other v1: 565,1820 607,1820 648,1820 565,1861 607,1861 646,1861 1369,2110
  other v2: 1845,1127 718.57,1178.87 772.9,1178.87 745.73,1208 718.57,1237.13 772.9,1237.13 1810,1560 1880,1560 1960,1560 1810,1615 1880,1615 1960,1615 1810,1670 1880,1670 1960,1670
\S\K\I\P\: Q3.3 R54.2 U2.3 | length 900.2
  Top Layer w8: Q3.3@1300,1344.5 1300,1302.18 1317,1285.18 1317,1246 v2(1338,1225) ; U2.3@1872.84,1089.6 1872.84,1065.16 v2(1890,1048) 1890,1016 1911.5,994.5 R54.2@1911.5,966
  Bottom Layer w8: v2(1338,1225) 1410,1225 1561,1074 1864,1074 v2(1890,1048)
COLLECTOR: D2.1 M1.5 | length 156.3
  Top Layer w30: D2.1@718,2283.74 718,2387.41 M1.5@755.2,2424.61
DESAT-DETECT: D6.2 R10.1 R51.1 R60.1 TP8.1 U3.1 | length 977.9
  Top Layer w15: R10.1@1298,1595.5 1332.2,1561.3 1332.2,1500.81 1396,1437.01 1396,1227.5 R60.1@1344.5,1176
  Top Layer w20: U3.1@1075.4,1727.24 1111.24,1727.24 1132.35,1748.35 D6.2@1201,1748.35 1201,1656 1261.5,1595.5 ; TP8.1@1203,1565.5 1231.51,1565.5 1261.5,1595.5 ; R51.1@1296,1671.5 1298,1669.5 R10.1@1298,1595.5 1261.5,1595.5
DRVH: Q1.3 R22.2 | length 275.6
  Top Layer w20: R22.2@1791,1304.5 1809.5,1323 1848.4,1323 1910,1384.6 Q1.3@1910,1508
DRVL: Q1.5 R26.2 | length 466.6
  Top Layer w20: Q1.5@1960,1720 1997,1720 2015,1702 2015,1357 1999,1341 R26.2@1999,1304.5
F\A\U\L\T\: J1.4 R27.1 R47.1 U1.5 | length 1151.2
  Top Layer w10: R47.1@1067,258.5 1067,210 1212,65 1564,65 J1.4@1629,130 1671.7,172.7 1671.7,332.2 R27.1@1708,368.5 ; U1.5@1610,480.87 1610,431 1610,421 1625,406 1668.54,406 1708.05,366.5 R27.1@1710,366.5
F\A\U\L\T\-\I\S\O\: Q4.3 R7.1 U1.12 | length 853.2
  Top Layer w8: Q4.3@1337.5,1448 1337.5,1424.5 1359,1403 R7.1@1359,1370.5 ; v2@1606,910 v2(1610,906) U1.12@1610,839.13
  Bottom Layer w8: v2(1345,1419) 1344,1419 1311,1386 1311,1132 1514,929 1572,929 1595,906 v2(1610,906)
GATE: C14.1 D18.1 M1.3 Q5.3 Q7.1 Q7.2 Q7.5 Q7.6 Q7.8 R2.1 R3.2 R5.2 R18.1 R34.1 R49.2 R55.2 R58.1 TP2.1 | length 958.5
  Top Layer w15: Q5.3@1162,2353.24 v1(1213.76,2353.24) ; R34.1@1206,1951.65 1213.35,1951.65 v1(1241,1924)
  Top Layer w30: M1.3@1805.2,2424.61 1845.59,2465 TP2.1@1999,2465
  Bottom Layer w15: v1(1213.76,2353.24) 1213.76,2175.24 1227.32,2161.68 1227.32,2022.32 1241,2008.64 v1(1241,1924)
  Bottom Layer w30: C14.1@1780,2237 1780,2280.73 1766.5,2294.24 R49.2@1766.5,2319 1766.5,2385.91 M1.3@1805.2,2424.61
GND: C1.2 C10.2 C19.2 C23.1 J1.6 R23.2 R25.2 R45.1 U1.2 U1.8 | length 703.5
  Top Layer w15: U1.8@1760,480.87 1825.13,480.87 v1(1864,442)
  Top Layer w20: v1(1207,209) R45.1@1207,257.5 ; v1(1440,239) C10.2@1440,305 1428.5,316.5 C1.2@1428.5,380 1430.5,380 1460,409.5 U1.2@1460,480.87 ; v1(1511,235) R23.2@1511,304.5 ; v1(1573,235) C23.1@1573,304.5 ; v1(1640,237) R25.2@1640,304.5 ; v1(1853,237) C19.2@1853,304.5
NetC5_1: C5.1 R1.1 | length 215
  Top Layer w20: v2(1755.03,1206.56) 1759.44,1206.56 1773,1193 1773,1192 1775,1190 R1.1@1775,1154.5 ; v2(1846,1234) 1857.5,1245.5 C5.1@1857.5,1279
  Bottom Layer w20: v2(1755.03,1206.56) 1818.56,1206.56 v2(1846,1234)
NetC8_1: C8.1 D5.1 Q6.3 R12.2 R14.1 TP6.1 U3.3 | length 417.9
  Top Layer w15: C8.1@933.5,1741 959,1741 972.76,1727.24 U3.3@1000.6,1727.24 ; D5.1@1004,1823.35 1027.65,1823.35 1041,1810 R14.1@1064.5,1810 TP6.1@1064.5,1874.5 TP6.1@1064,1875
  Top Layer w20: C8.1@933.5,1741 C8.1@933.5,1743 933.5,1767.7 946.5,1780.7 R12.2@946.5,1809 ; Q6.3@946.5,1886 R12.2@946.5,1809 ; D5.1@1004,1823.35 982.35,1823.35 968,1809 R12.2@946.5,1809
NetC18_2: C18.2 R28.1 R29.2 U4.2 | length 245.4
  Top Layer w15: U4.2@828.41,1195.2 887.71,1195.2 919,1226.5 C18.2@923,1226.5 ; R29.2@918,1297.23 923,1292.23 C18.2@923,1226.5 ; R28.1@988,1226.5 C18.2@923,1226.5
NetC19_1: C19.1 R20.1 U1.7 | length 225.6
  Top Layer w10: U1.7@1710,470 1710,429 1719.82,419.18 1760.82,419.18 1785,395 R20.1@1785,367.5 C19.1@1853,367.5
NetC20_1: C20.1 R21.2 U1.10 | length 165
  Top Layer w10: U1.10@1710,839.13 1710,931.5 R21.2@1709,932.5 1776,932.5 C20.1@1779,935.5
NetC21_1: C21.1 D4.1 R4.1 TP4.1 U3.4 | length 432.1
  Top Layer w20: TP4.1@774,1663 774,1616 809.5,1580.5 R4.1@869,1580.5 C21.1@939,1580.5 ; D4.1@922.53,1484 922.53,1512.53 939,1529 C21.1@939,1580.5 ; U3.4@1000.6,1632.76 1000.6,1600.6 980.5,1580.5 C21.1@939,1580.5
